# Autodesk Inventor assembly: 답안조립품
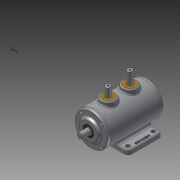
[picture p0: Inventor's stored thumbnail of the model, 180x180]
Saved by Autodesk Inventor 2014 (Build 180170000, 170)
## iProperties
Created: 2014-12
Part Number: 답안조립품
Document SubType Name: Assembly
Designer: Owner
Author: Owner
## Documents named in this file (10)
- C:\Users\Owner\Desktop\441223V1006\답안조립품.iam
- C:\Users\Owner\Desktop\441223V1006\본체.ipt
- C:\Users\Owner\Desktop\441223V1006\M4-소켓머리.ipt
- C:\Users\Owner\Desktop\441223V1006\뒷커버.ipt
- C:\Users\Owner\Desktop\441223V1006\베어링 6203.ipt
- C:\Users\Owner\Desktop\441223V1006\부시.ipt
- C:\Users\Owner\Desktop\441223V1006\슬라이더.ipt
- C:\Users\Owner\Desktop\441223V1006\앞커버.ipt
- C:\Users\Owner\Desktop\441223V1006\오일실.ipt
- C:\Users\Owner\Desktop\441223V1006\축.ipt
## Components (4 placed, 3 different names)
1. 9-M4-소켓머리:1
2. 7-베어링 6203:1
3. 8-오일실:1
4. 7-베어링 6203:2
